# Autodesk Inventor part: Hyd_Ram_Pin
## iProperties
Created: 2005-03
Part Number: Hyd_Ram_Pin
Document SubType Name: Modeling
Designer: brent
Density: 1 g/cm^3
Author: Autodesk Inc.
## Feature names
1. Extrusion1
